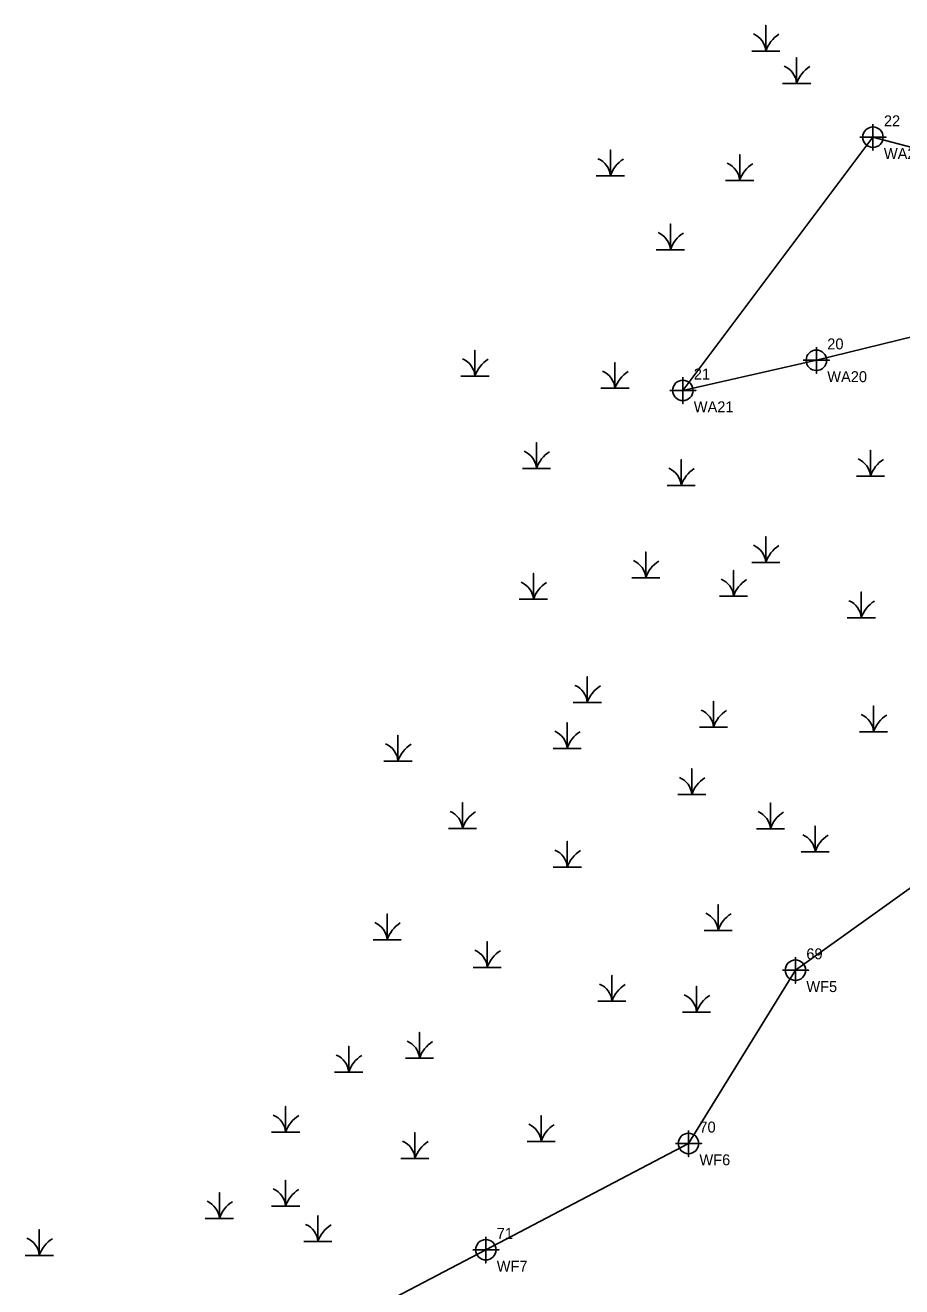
# Model space of a CAD drawing. Extents: x 2189822 to 2191198, y 387253 to 388663.
# Drawn here: x 2190035.9 to 2190236.7, y 387833.3 to 388122.3 of the extents above; entities that cross this region are included whole.
import ezdxf

# ---------------------------------------------------------------- set-up
doc = ezdxf.new("R2010")
doc.units = 0
for name, color, linetype in [('Structure020030_Alleghany', 7, 'Continuous'), ('Structure040008_Ashe', 7, 'Continuous'), ('Structure090007_Brunswick', 7, 'Continuous'), ('Structure620024_Moore', 7, 'Continuous'), ('Structure780124_Rockingham', 7, 'Continuous')]:
    doc.layers.add(name, color=color, linetype=linetype)

msp = doc.modelspace()

# ---------------------------------------------------------------- linework, layer by layer
at = {"layer": 'Structure020030_Alleghany'}
for points in [[(2190230.07, 388099.61), (2190230.07, 388093.61), (2190230.07, 388096.61), (2190233.07, 388096.61), (2190227.07, 388096.61)], [(2190217.1, 388048.51), (2190217.1, 388042.51), (2190217.1, 388045.51), (2190220.1, 388045.51), (2190214.1, 388045.51)], [(2190186.53, 388041.61), (2190186.53, 388035.61), (2190186.53, 388038.61), (2190189.53, 388038.61), (2190183.53, 388038.61)], [(2190212.31, 387908.81), (2190212.31, 387902.81), (2190212.31, 387905.81), (2190215.31, 387905.81), (2190209.31, 387905.81)], [(2190187.82, 387869.13), (2190187.82, 387863.13), (2190187.82, 387866.13), (2190190.82, 387866.13), (2190184.82, 387866.13)], [(2190141.4, 387844.78), (2190141.4, 387838.78), (2190141.4, 387841.78), (2190144.4, 387841.78), (2190138.4, 387841.78)]]:
    msp.add_lwpolyline(points, dxfattribs=at)
for centre in [(2190230.07, 388096.61), (2190217.1, 388045.51), (2190186.53, 388038.61), (2190212.31, 387905.81), (2190187.82, 387866.13), (2190141.4, 387841.78)]:
    msp.add_circle(centre, 2.34, dxfattribs=at)
at = {"layer": 'Structure620024_Moore'}
for points in [[(2190246.78, 388052.8), (2190217.1, 388045.51), (2190186.53, 388038.61), (2190230.07, 388096.61), (2190250.93, 388091.14)], [(2190311.6, 387912.32), (2190282.87, 387902.15), (2190276.9, 387926.61), (2190246.66, 387930.44), (2190212.31, 387905.81), (2190187.82, 387866.13), (2190141.4, 387841.78), (2190098.41, 387819.25)]]:
    msp.add_lwpolyline(points, dxfattribs=at)
at = {"layer": 'Structure780124_Rockingham'}
for p, q in [((2190205.53, 388119.01), (2190205.53, 388119.01)), ((2190212.58, 388111.61), (2190212.58, 388111.61)), ((2190169.93, 388090.44), (2190169.93, 388090.44)), ((2190199.54, 388089.38), (2190199.54, 388089.38)), ((2190183.67, 388073.51), (2190183.67, 388073.51)), ((2190138.9, 388044.58), (2190138.9, 388044.58)), ((2190170.98, 388041.76), (2190170.98, 388041.76)), ((2190153, 388023.42), (2190153, 388023.42)), ((2190186.14, 388019.54), (2190186.14, 388019.54)), ((2190229.5, 388021.65), (2190229.5, 388021.65)), ((2190205.53, 388001.9), (2190205.53, 388001.9)), ((2190178.03, 387998.37), (2190178.03, 387998.37)), ((2190152.3, 387993.43), (2190152.3, 387993.43)), ((2190198.13, 387994.14), (2190198.13, 387994.14)), ((2190227.39, 387989.2), (2190227.39, 387989.2)), ((2190164.64, 387969.8), (2190164.64, 387969.8)), ((2190193.55, 387964.16), (2190193.55, 387964.16)), ((2190230.21, 387963.1), (2190230.21, 387963.1)), ((2190160.02, 387959.29), (2190160.02, 387959.29)), ((2190121.28, 387956.39), (2190121.28, 387956.39)), ((2190188.57, 387948.7), (2190188.57, 387948.7)), ((2190136.05, 387940.94), (2190136.05, 387940.94)), ((2190206.59, 387940.87), (2190206.59, 387940.87)), ((2190216.81, 387935.58), (2190216.81, 387935.58)), ((2190160.06, 387932.05), (2190160.06, 387932.05)), ((2190118.81, 387915.48), (2190118.81, 387915.48)), ((2190194.6, 387917.59), (2190194.6, 387917.59)), ((2190141.72, 387909.13), (2190141.72, 387909.13)), ((2190170.28, 387901.37), (2190170.28, 387901.37)), ((2190189.67, 387898.9), (2190189.67, 387898.9)), ((2190126.21, 387888.31), (2190126.21, 387888.31)), ((2190110, 387885.14), (2190110, 387885.14)), ((2190095.54, 387871.38), (2190095.54, 387871.38)), ((2190154.06, 387869.26), (2190154.06, 387869.26)), ((2190125.16, 387865.38), (2190125.16, 387865.38)), ((2190095.54, 387854.45), (2190095.54, 387854.45)), ((2190080.38, 387851.63), (2190080.38, 387851.63)), ((2190102.95, 387846.34), (2190102.95, 387846.34)), ((2190039.14, 387843.16), (2190039.14, 387843.16))]:
    msp.add_line(p, q, dxfattribs=at)
for points in [[(2190202.31, 388116.34), (2190205.53, 388116.34), (2190205.53, 388122.26), (2190205.53, 388116.34), (2190208.76, 388116.34)], [(2190209.36, 388108.93), (2190212.58, 388108.93), (2190212.58, 388114.85), (2190212.58, 388108.93), (2190215.81, 388108.93)], [(2190166.7, 388087.77), (2190169.93, 388087.77), (2190169.93, 388093.68), (2190169.93, 388087.77), (2190173.15, 388087.77)], [(2190196.31, 388086.71), (2190199.54, 388086.71), (2190199.54, 388092.63), (2190199.54, 388086.71), (2190202.76, 388086.71)], [(2190180.45, 388070.83), (2190183.68, 388070.83), (2190183.68, 388076.75), (2190183.68, 388070.83), (2190186.9, 388070.83)], [(2190135.68, 388041.91), (2190138.9, 388041.91), (2190138.9, 388047.83), (2190138.9, 388041.91), (2190142.13, 388041.91)], [(2190167.76, 388039.09), (2190170.98, 388039.09), (2190170.98, 388045), (2190170.98, 388039.09), (2190174.21, 388039.09)], [(2190149.78, 388020.74), (2190153.01, 388020.74), (2190153.01, 388026.66), (2190153.01, 388020.74), (2190156.23, 388020.74)], [(2190182.92, 388016.86), (2190186.14, 388016.86), (2190186.14, 388022.78), (2190186.14, 388016.86), (2190189.37, 388016.86)], [(2190226.28, 388018.98), (2190229.5, 388018.98), (2190229.5, 388024.9), (2190229.5, 388018.98), (2190232.73, 388018.98)], [(2190202.31, 387999.23), (2190205.53, 387999.23), (2190205.53, 388005.14), (2190205.53, 387999.23), (2190208.76, 387999.23)], [(2190174.81, 387995.7), (2190178.03, 387995.7), (2190178.03, 388001.62), (2190178.03, 387995.7), (2190181.26, 387995.7)], [(2190149.07, 387990.76), (2190152.3, 387990.76), (2190152.3, 387996.68), (2190152.3, 387990.76), (2190155.53, 387990.76)], [(2190194.9, 387991.46), (2190198.13, 387991.46), (2190198.13, 387997.38), (2190198.13, 387991.46), (2190201.35, 387991.46)], [(2190224.16, 387986.53), (2190227.39, 387986.53), (2190227.39, 387992.44), (2190227.39, 387986.53), (2190230.61, 387986.53)], [(2190161.41, 387967.12), (2190164.64, 387967.12), (2190164.64, 387973.04), (2190164.64, 387967.12), (2190167.86, 387967.12)], [(2190190.32, 387961.48), (2190193.55, 387961.48), (2190193.55, 387967.4), (2190193.55, 387961.48), (2190196.77, 387961.48)], [(2190226.98, 387960.42), (2190230.21, 387960.42), (2190230.21, 387966.34), (2190230.21, 387960.42), (2190233.43, 387960.42)], [(2190156.79, 387956.61), (2190160.02, 387956.61), (2190160.02, 387962.53), (2190160.02, 387956.61), (2190163.24, 387956.61)], [(2190118.05, 387953.72), (2190121.28, 387953.72), (2190121.28, 387959.64), (2190121.28, 387953.72), (2190124.5, 387953.72)], [(2190185.35, 387946.03), (2190188.57, 387946.03), (2190188.57, 387951.95), (2190188.57, 387946.03), (2190191.8, 387946.03)], [(2190132.82, 387938.27), (2190136.05, 387938.27), (2190136.05, 387944.19), (2190136.05, 387938.27), (2190139.27, 387938.27)], [(2190203.36, 387938.2), (2190206.59, 387938.2), (2190206.59, 387944.12), (2190206.59, 387938.2), (2190209.82, 387938.2)], [(2190213.59, 387932.91), (2190216.81, 387932.91), (2190216.81, 387938.83), (2190216.81, 387932.91), (2190220.04, 387932.91)], [(2190156.83, 387929.38), (2190160.06, 387929.38), (2190160.06, 387935.3), (2190160.06, 387929.38), (2190163.28, 387929.38)], [(2190115.59, 387912.8), (2190118.81, 387912.8), (2190118.81, 387918.72), (2190118.81, 387912.8), (2190122.04, 387912.8)], [(2190191.38, 387914.92), (2190194.6, 387914.92), (2190194.6, 387920.84), (2190194.6, 387914.92), (2190197.83, 387914.92)], [(2190138.5, 387906.45), (2190141.72, 387906.45), (2190141.72, 387912.37), (2190141.72, 387906.45), (2190144.95, 387906.45)], [(2190167.05, 387898.69), (2190170.28, 387898.69), (2190170.28, 387904.61), (2190170.28, 387898.69), (2190173.5, 387898.69)], [(2190186.44, 387896.22), (2190189.67, 387896.22), (2190189.67, 387902.14), (2190189.67, 387896.22), (2190192.89, 387896.22)], [(2190122.99, 387885.64), (2190126.21, 387885.64), (2190126.21, 387891.56), (2190126.21, 387885.64), (2190129.44, 387885.64)], [(2190106.77, 387882.46), (2190110, 387882.46), (2190110, 387888.38), (2190110, 387882.46), (2190113.22, 387882.46)], [(2190092.32, 387868.71), (2190095.54, 387868.71), (2190095.54, 387874.62), (2190095.54, 387868.71), (2190098.77, 387868.71)], [(2190150.84, 387866.59), (2190154.06, 387866.59), (2190154.06, 387872.51), (2190154.06, 387866.59), (2190157.29, 387866.59)], [(2190121.93, 387862.71), (2190125.16, 387862.71), (2190125.16, 387868.63), (2190125.16, 387862.71), (2190128.38, 387862.71)], [(2190092.32, 387851.77), (2190095.54, 387851.77), (2190095.54, 387857.69), (2190095.54, 387851.77), (2190098.77, 387851.77)], [(2190077.16, 387848.95), (2190080.39, 387848.95), (2190080.39, 387854.87), (2190080.39, 387848.95), (2190083.61, 387848.95)], [(2190099.72, 387843.66), (2190102.95, 387843.66), (2190102.95, 387849.58), (2190102.95, 387843.66), (2190106.17, 387843.66)], [(2190035.91, 387840.49), (2190039.14, 387840.49), (2190039.14, 387846.4), (2190039.14, 387840.49), (2190042.37, 387840.49)]]:
    msp.add_lwpolyline(points, dxfattribs=at)
for centre, radius, start, end in [((2190200.93, 388116.01), 4.61, 4.1403, 67.535), ((2190212.37, 388114.07), 7.21, 122.1274, 161.6222), ((2190207.98, 388108.6), 4.61, 4.1403, 67.535), ((2190219.42, 388106.66), 7.21, 122.1274, 161.6222), ((2190165.33, 388087.43), 4.61, 4.1403, 67.535), ((2190176.77, 388085.49), 7.21, 122.1274, 161.6222), ((2190194.94, 388086.37), 4.61, 4.1403, 67.535), ((2190206.38, 388084.43), 7.21, 122.1274, 161.6222), ((2190179.08, 388070.5), 4.61, 4.1403, 67.535), ((2190190.52, 388068.56), 7.21, 122.1274, 161.6222), ((2190134.3, 388041.57), 4.61, 4.1403, 67.535), ((2190145.75, 388039.64), 7.21, 122.1274, 161.6222), ((2190166.38, 388038.75), 4.61, 4.1403, 67.535), ((2190177.83, 388036.81), 7.21, 122.1274, 161.6222), ((2190148.41, 388020.41), 4.61, 4.1403, 67.535), ((2190159.85, 388018.47), 7.21, 122.1274, 161.6222), ((2190224.9, 388018.65), 4.61, 4.1403, 67.535), ((2190236.34, 388016.71), 7.21, 122.1274, 161.6222), ((2190181.54, 388016.53), 4.61, 4.1403, 67.535), ((2190192.98, 388014.59), 7.21, 122.1274, 161.6222), ((2190200.93, 387998.89), 4.61, 4.1403, 67.535), ((2190212.37, 387996.95), 7.21, 122.1274, 161.6222), ((2190173.44, 387995.36), 4.61, 4.1403, 67.535), ((2190184.88, 387993.42), 7.21, 122.1274, 161.6222), ((2190147.7, 387990.43), 4.61, 4.1403, 67.535), ((2190159.14, 387988.49), 7.21, 122.1274, 161.6222), ((2190193.53, 387991.13), 4.61, 4.1403, 67.535), ((2190204.97, 387989.19), 7.21, 122.1274, 161.6222), ((2190222.79, 387986.19), 4.61, 4.1403, 67.535), ((2190234.23, 387984.25), 7.21, 122.1274, 161.6222), ((2190160.04, 387966.79), 4.61, 4.1403, 67.535), ((2190171.48, 387964.85), 7.21, 122.1274, 161.6222), ((2190188.95, 387961.15), 4.61, 4.1403, 67.535), ((2190200.39, 387959.21), 7.21, 122.1274, 161.6222), ((2190225.61, 387960.09), 4.61, 4.1403, 67.535), ((2190237.05, 387958.15), 7.21, 122.1274, 161.6222), ((2190155.42, 387956.28), 4.61, 4.1403, 67.535), ((2190166.86, 387954.34), 7.21, 122.1274, 161.6222), ((2190116.68, 387953.39), 4.61, 4.1403, 67.535), ((2190128.12, 387951.45), 7.21, 122.1274, 161.6222), ((2190183.97, 387945.7), 4.61, 4.1403, 67.535), ((2190195.41, 387943.76), 7.21, 122.1274, 161.6222), ((2190131.45, 387937.93), 4.61, 4.1403, 67.535), ((2190142.89, 387936), 7.21, 122.1274, 161.6222), ((2190201.99, 387937.87), 4.61, 4.1403, 67.535), ((2190213.43, 387935.93), 7.21, 122.1274, 161.6222), ((2190212.21, 387932.57), 4.61, 4.1403, 67.535), ((2190223.65, 387930.64), 7.21, 122.1274, 161.6222), ((2190155.46, 387929.05), 4.61, 4.1403, 67.535), ((2190166.9, 387927.11), 7.21, 122.1274, 161.6222), ((2190190, 387914.58), 4.61, 4.1403, 67.535), ((2190201.44, 387912.64), 7.21, 122.1274, 161.6222), ((2190114.21, 387912.47), 4.61, 4.1403, 67.535), ((2190125.65, 387910.53), 7.21, 122.1274, 161.6222), ((2190137.12, 387906.12), 4.61, 4.1403, 67.535), ((2190148.57, 387904.18), 7.21, 122.1274, 161.6222), ((2190165.68, 387898.36), 4.61, 4.1403, 67.535), ((2190177.12, 387896.42), 7.21, 122.1274, 161.6222), ((2190185.07, 387895.89), 4.61, 4.1403, 67.535), ((2190196.51, 387893.95), 7.21, 122.1274, 161.6222), ((2190121.61, 387885.31), 4.61, 4.1403, 67.535), ((2190133.05, 387883.37), 7.21, 122.1274, 161.6222), ((2190105.4, 387882.13), 4.61, 4.1403, 67.535), ((2190116.84, 387880.19), 7.21, 122.1274, 161.6222), ((2190090.94, 387868.37), 4.61, 4.1403, 67.535), ((2190102.38, 387866.43), 7.21, 122.1274, 161.6222), ((2190149.46, 387866.26), 4.61, 4.1403, 67.535), ((2190160.9, 387864.32), 7.21, 122.1274, 161.6222), ((2190120.56, 387862.38), 4.61, 4.1403, 67.535), ((2190132, 387860.44), 7.21, 122.1274, 161.6222), ((2190090.94, 387851.44), 4.61, 4.1403, 67.535), ((2190102.38, 387849.5), 7.21, 122.1274, 161.6222), ((2190075.79, 387848.62), 4.61, 4.1403, 67.535), ((2190087.23, 387846.68), 7.21, 122.1274, 161.6222), ((2190098.35, 387843.33), 4.61, 4.1403, 67.535), ((2190109.79, 387841.39), 7.21, 122.1274, 161.6222), ((2190034.54, 387840.15), 4.61, 4.1403, 67.535), ((2190045.98, 387838.21), 7.21, 122.1274, 161.6222)]:
    msp.add_arc(centre, radius, start, end, dxfattribs=at)

# ---------------------------------------------------------------- texts
at = {"layer": 'Structure040008_Ashe'}
for s, p in [('22', (2190232.57, 388099.11)), ('20', (2190219.6, 388048.01)), ('21', (2190189.03, 388041.11)), ('69', (2190214.81, 387908.31)), ('70', (2190190.32, 387868.63)), ('71', (2190143.9, 387844.28))]:
    msp.add_text(s, height=2.5, dxfattribs=at).set_placement(p)
at = {"layer": 'Structure090007_Brunswick'}
for s, p in [('WA22', (2190232.57, 388091.61)), ('WA20', (2190219.6, 388040.51)), ('WA21', (2190189.03, 388033.61)), ('WF5', (2190214.81, 387900.81)), ('WF6', (2190190.32, 387861.13)), ('WF7', (2190143.9, 387836.78))]:
    msp.add_text(s, height=2.5, dxfattribs=at).set_placement(p)

doc.saveas('drawing.dxf')
